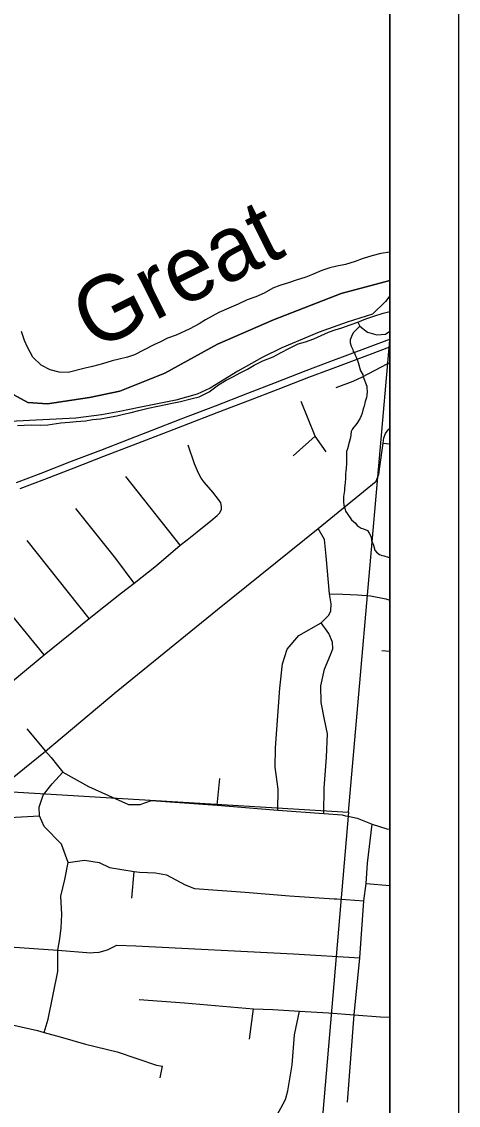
# Model space of a CAD drawing. Extents: x 0 to 34, y 0 to 22.
# Drawn here: x 8.362 to 9, y 18.183 to 19.765 of the extents above; entities that cross this region are included whole.
import ezdxf

# ---------------------------------------------------------------- set-up
doc = ezdxf.new("R2010")
doc.units = 0
for name, color, linetype in [('GM_X_City_Street', 7, 'Continuous'), ('GM_X_Corporation', 7, 'Continuous'), ('GM_X_County_Road', 7, 'Continuous'), ('GM_X_Major_River', 7, 'Continuous'), ('GM_X_Major_River_Text', 7, 'Continuous'), ('GM_X_Minor_River', 7, 'Continuous'), ('GM_X_State_Route', 7, 'Continuous'), ('SH_Data', 7, 'Continuous')]:
    doc.layers.add(name, color=color, linetype=linetype)

msp = doc.modelspace()

# ---------------------------------------------------------------- linework, layer by layer
at = {"layer": 'GM_X_City_Street'}
for p, q in [((8.7588, 19.1313), (8.7908, 19.1601)), ((8.5934, 19.0006), (8.5138, 19.101)), ((8.4606, 18.8937), (8.3698, 19.0073)), ((8.8883, 18.8469), (8.9, 18.8458)), ((8.6477, 18.6209), (8.6514, 18.6598)), ((8.2709, 18.5986), (8.3877, 18.6055)), ((8.5227, 18.4849), (8.5262, 18.5239)), ((8.8652, 18.5066), (8.9, 18.5036)), ((8.8223, 18.484), (8.8619, 18.481)), ((8.6947, 18.2791), (8.7005, 18.3236)), ((8.5642, 18.2229), (8.5677, 18.2397))]:
    msp.add_line(p, q, dxfattribs=at)
for points in [[(8.8215, 19.2312), (8.8463, 19.2404), (8.8597, 19.2465), (8.8958, 19.2654), (8.9, 19.2677)], [(8.8069, 19.137), (8.7908, 19.1601), (8.7701, 19.2104)], [(8.8899, 19.1495), (8.8911, 19.1574), (8.8937, 19.1638), (8.8974, 19.1693), (8.9, 19.1716)], [(8.654, 19.0528), (8.6539, 19.0573), (8.6527, 19.0623), (8.6494, 19.0676), (8.6412, 19.078), (8.6286, 19.0929), (8.6241, 19.0985), (8.62, 19.1059), (8.6145, 19.1193), (8.605, 19.1469)], [(8.88, 19.0943), (8.884, 19.1046), (8.8855, 19.1153), (8.8899, 19.1495)], [(7.9604, 18.3429), (8.0785, 18.443), (8.1263, 18.4819), (8.1779, 18.5241), (8.2709, 18.5986), (8.3967, 18.6996), (8.5001, 18.7867), (8.6479, 18.9068), (8.7952, 19.025), (8.88, 19.0943)], [(7.9831, 18.5148), (8.0096, 18.527), (8.0601, 18.5672), (8.1876, 18.6723), (8.1944, 18.6785), (8.2608, 18.7319), (8.3278, 18.7857), (8.3946, 18.8403), (8.4606, 18.8937), (8.4843, 18.9125), (8.5075, 18.931), (8.526, 18.9454), (8.5589, 18.9711), (8.5934, 19.0006), (8.6038, 19.0083), (8.6182, 19.0203), (8.6383, 19.0363), (8.6474, 19.0438), (8.6507, 19.0475), (8.654, 19.0528)], [(8.526, 18.9454), (8.4992, 18.9813), (8.4412, 19.0541)], [(8.7361, 18.6138), (8.7367, 18.6445), (8.7324, 18.6766), (8.7328, 18.7047), (8.739, 18.7917), (8.743, 18.8272), (8.7497, 18.8489), (8.7671, 18.8689), (8.7994, 18.8875), (8.8106, 18.8984), (8.8137, 18.9049), (8.8142, 18.9149), (8.8119, 18.9298), (8.8068, 18.9844), (8.8046, 19.0092), (8.7952, 19.025)], [(8.3946, 18.8403), (8.3276, 18.9225), (8.3187, 18.9352), (8.3103, 18.9485), (8.302, 18.9648)], [(8.8119, 18.9298), (8.8314, 18.9292), (8.8527, 18.928), (8.8717, 18.9267), (8.894, 18.9221), (8.9, 18.9205)], [(8.8032, 18.609), (8.8038, 18.6457), (8.8074, 18.691), (8.809, 18.7252), (8.8046, 18.7463), (8.7996, 18.771), (8.7991, 18.7952), (8.8046, 18.8194), (8.813, 18.8406), (8.8165, 18.8495), (8.8162, 18.8592), (8.8105, 18.8716), (8.7994, 18.8875)], [(8.3694, 18.7326), (8.3967, 18.6996), (8.4047, 18.6905), (8.4142, 18.6789), (8.4222, 18.669), (8.4597, 18.6483), (8.5177, 18.6218), (8.5349, 18.6218), (8.5514, 18.6279), (8.6477, 18.6209), (8.7361, 18.6138), (8.8032, 18.609), (8.8302, 18.6066), (8.8352, 18.6056)], [(8.3945, 18.2887), (8.4007, 18.3083), (8.4147, 18.3779), (8.4148, 18.4093), (8.4174, 18.4259), (8.4194, 18.442), (8.4204, 18.4614), (8.4189, 18.488), (8.4251, 18.5125), (8.4297, 18.537), (8.4198, 18.5639), (8.3945, 18.5897), (8.3877, 18.6055), (8.3874, 18.6178), (8.3932, 18.6358), (8.4063, 18.6523), (8.4222, 18.669)], [(8.8352, 18.6056), (8.8411, 18.6044), (8.8521, 18.6022), (8.874, 18.5933), (8.8953, 18.5863), (8.9, 18.5858)], [(8.8378, 18.1872), (8.8479, 18.3148), (8.8558, 18.3979), (8.8619, 18.481), (8.8652, 18.5066), (8.8673, 18.5364), (8.874, 18.5933)], [(8.4297, 18.537), (8.4534, 18.5408), (8.4749, 18.5373), (8.4903, 18.5299), (8.5262, 18.5239), (8.5338, 18.5229), (8.5574, 18.5219), (8.5737, 18.5194), (8.6009, 18.5044), (8.6143, 18.4993), (8.6886, 18.4938), (8.7532, 18.4886), (8.8183, 18.4843), (8.8223, 18.484)], [(8.0785, 18.443), (8.0916, 18.4385), (8.1341, 18.4343), (8.3091, 18.4164), (8.4148, 18.4093), (8.463, 18.4055), (8.467, 18.4057)], [(8.467, 18.4057), (8.4749, 18.4061), (8.4871, 18.4098), (8.5008, 18.4164), (8.5288, 18.4155), (8.7593, 18.4037), (8.8558, 18.3979)], [(7.5944, 18.3779), (7.6439, 18.3725), (7.6838, 18.3682), (7.7475, 18.3614), (7.8193, 18.3552), (7.8216, 18.355), (7.8546, 18.3522), (7.9604, 18.3429), (7.9962, 18.3397), (8.0146, 18.3381), (8.0724, 18.3329), (8.1174, 18.3288), (8.2145, 18.3208), (8.2997, 18.3107), (8.3851, 18.2916), (8.3945, 18.2887), (8.4179, 18.2828), (8.4549, 18.2717), (8.5013, 18.2607), (8.559, 18.2414), (8.5677, 18.2397)], [(8.5337, 18.3373), (8.5997, 18.3321), (8.7005, 18.3236), (8.7291, 18.3227), (8.7679, 18.32), (8.8104, 18.3175), (8.8479, 18.3148), (8.8862, 18.312), (8.9, 18.3112)], [(8.7799, 17.9607), (8.7514, 17.9623), (8.7401, 17.9675), (8.7297, 17.9787), (8.7228, 17.9955), (8.7215, 18.0263), (8.7285, 18.0726), (8.7308, 18.0957), (8.7272, 18.1228), (8.7259, 18.1403), (8.7331, 18.1653), (8.7406, 18.1786), (8.7472, 18.191), (8.751, 18.2035), (8.7572, 18.2416), (8.7607, 18.2853), (8.7679, 18.32)]]:
    msp.add_lwpolyline(points, dxfattribs=at)
at = {"layer": 'GM_X_Corporation'}
for points in [[(8.2412, 20.0451), (8.2346, 19.7113), (8.2293, 19.3521), (8.274, 19.3267), (8.2967, 19.3032), (8.3059, 19.2949), (8.3138, 19.2837), (8.3245, 19.2617), (8.3344, 19.2397), (8.3504, 19.2202), (8.3709, 19.2089), (8.3996, 19.2072), (8.461, 19.2162), (8.5053, 19.2254), (8.5711, 19.2518), (8.648, 19.2941), (8.73, 19.3298), (8.8288, 19.3684), (8.9, 19.3874), (8.9, 20.898)], [(8.9, 14.098), (8.9, 19.3874), (8.8288, 19.3684), (8.73, 19.3298), (8.648, 19.2941), (8.5711, 19.2518), (8.5053, 19.2254), (8.461, 19.2162), (8.3996, 19.2072), (8.3709, 19.2089), (8.3504, 19.2202), (8.3344, 19.2397), (8.3245, 19.2617), (8.3138, 19.2837), (8.3059, 19.2949), (8.2967, 19.3032), (8.274, 19.3267), (8.2293, 19.3521), (8.2346, 19.7113), (8.2412, 20.0451)], [(7.7682, 18.6757), (8.8396, 18.6106), (8.9, 19.3002), (8.9, 19.3647), (8.8935, 19.3564), (8.8746, 19.3383), (8.8373, 19.3265), (8.7964, 19.3118), (8.7418, 19.289), (8.7131, 19.2748), (8.6775, 19.2547), (8.6372, 19.2298), (8.6185, 19.2214), (8.5869, 19.2126), (8.5337, 19.2019), (8.5055, 19.1961), (8.4785, 19.1909), (8.4409, 19.186), (8.3446, 19.1811)], [(8.9, 14.098), (8.9, 19.185)], [(7.7459, 18.2415), (7.7682, 18.6757), (8.8396, 18.6106), (8.7511, 17.5795), (7.7161, 17.6636), (7.7361, 18.0529)]]:
    msp.add_lwpolyline(points, dxfattribs=at)
at = {"layer": 'GM_X_County_Road'}
msp.add_line((8.8899, 19.1495), (8.9, 19.1485), dxfattribs=at)
at = {"layer": 'GM_X_Major_River'}
for points in [[(8.9, 19.4286), (8.8869, 19.4265), (8.8736, 19.4233), (8.8594, 19.419), (8.8491, 19.4151)], [(8.9, 19.4286), (8.8869, 19.4265), (8.8736, 19.4233), (8.8594, 19.419), (8.8491, 19.4151)], [(8.8491, 19.4151), (8.835, 19.4108), (8.8224, 19.408), (8.8121, 19.4056), (8.8006, 19.402), (8.7868, 19.3962), (8.7769, 19.3922), (8.7631, 19.3876), (8.7532, 19.3844), (8.7391, 19.3801), (8.7291, 19.3761), (8.716, 19.3688), (8.7038, 19.3634), (8.6915, 19.3591), (8.6781, 19.3525), (8.6647, 19.3467), (8.6498, 19.3405), (8.6402, 19.335), (8.6306, 19.3299), (8.621, 19.324), (8.6075, 19.3167), (8.5876, 19.3073), (8.575, 19.303), (8.5646, 19.2979), (8.555, 19.2935), (8.5266, 19.2789), (8.5163, 19.2753), (8.5045, 19.2725), (8.4942, 19.2701), (8.4797, 19.2658), (8.4655, 19.2619), (8.4548, 19.2591), (8.4297, 19.2528), (8.4164, 19.2534), (8.4036, 19.2567), (8.3904, 19.2635), (8.3782, 19.2755), (8.3701, 19.2897), (8.3658, 19.2997), (8.3615, 19.313)], [(8.8491, 19.4151), (8.835, 19.4108), (8.8224, 19.408), (8.8121, 19.4056), (8.8006, 19.402), (8.7868, 19.3962), (8.7769, 19.3922), (8.7631, 19.3876), (8.7532, 19.3844), (8.7391, 19.3801), (8.7291, 19.3761), (8.716, 19.3688), (8.7038, 19.3634), (8.6915, 19.3591), (8.6781, 19.3525), (8.6647, 19.3467), (8.6498, 19.3405), (8.6402, 19.335), (8.6306, 19.3299), (8.621, 19.324), (8.6075, 19.3167), (8.5876, 19.3073), (8.575, 19.303), (8.5646, 19.2979), (8.555, 19.2935), (8.5266, 19.2789), (8.5163, 19.2753), (8.5045, 19.2725), (8.4942, 19.2701), (8.4797, 19.2658), (8.4655, 19.2619), (8.4548, 19.2591), (8.4297, 19.2528), (8.4164, 19.2534), (8.4036, 19.2567), (8.3904, 19.2635), (8.3782, 19.2755), (8.3701, 19.2897), (8.3658, 19.2997), (8.3615, 19.313)], [(8.3555, 19.1757), (8.3654, 19.1762), (8.3756, 19.1764), (8.3893, 19.1761), (8.3999, 19.1767), (8.4189, 19.1793), (8.4315, 19.1802), (8.4414, 19.1811), (8.4551, 19.1824), (8.4653, 19.1841), (8.4771, 19.1853), (8.487, 19.187), (8.5008, 19.1898), (8.5107, 19.1919), (8.5217, 19.1947), (8.5332, 19.1975), (8.5469, 19.201), (8.561, 19.2038), (8.5816, 19.2079), (8.5938, 19.2107), (8.6091, 19.2145), (8.6213, 19.2173), (8.6358, 19.2246), (8.6497, 19.235), (8.6609, 19.2416), (8.6713, 19.2471), (8.6812, 19.2526), (8.692, 19.258), (8.7016, 19.2635), (8.7142, 19.2697), (8.7292, 19.2759), (8.7403, 19.2817), (8.753, 19.2883), (8.766, 19.2949), (8.7767, 19.2977), (8.7886, 19.302), (8.7997, 19.3071), (8.81, 19.3118), (8.82, 19.3154), (8.8295, 19.3179), (8.8421, 19.3226), (8.8529, 19.3265), (8.8647, 19.3312), (8.8781, 19.3359), (8.8899, 19.3394), (8.9, 19.342)]]:
    msp.add_lwpolyline(points, dxfattribs=at)
at = {"layer": 'GM_X_Minor_River'}
for points in [[(8.8529, 19.3265), (8.8561, 19.3207), (8.867, 19.3118), (8.8809, 19.3081), (8.8935, 19.309), (8.9, 19.3131)], [(8.8561, 19.3207), (8.8463, 19.3107), (8.8439, 19.3054), (8.842, 19.3004), (8.842, 19.2963), (8.8435, 19.2913), (8.8457, 19.2864), (8.8461, 19.2837), (8.8483, 19.281), (8.8494, 19.278), (8.8505, 19.2753), (8.8524, 19.2704), (8.8535, 19.2677), (8.8572, 19.2555), (8.8602, 19.2502), (8.8609, 19.2468), (8.8661, 19.2331), (8.8665, 19.2297), (8.8668, 19.2255), (8.8664, 19.2194), (8.8656, 19.2164), (8.8637, 19.2107), (8.8625, 19.2035), (8.861, 19.1998), (8.8594, 19.1937), (8.8582, 19.1895), (8.8559, 19.1854), (8.854, 19.1824), (8.8525, 19.1797), (8.8502, 19.1767), (8.8468, 19.1726), (8.8448, 19.1696), (8.8433, 19.1669), (8.8425, 19.1578), (8.8409, 19.1525), (8.8378, 19.1412), (8.8367, 19.1374), (8.8366, 19.1207), (8.8361, 19.1127), (8.8357, 19.1093), (8.8353, 19.1044), (8.8353, 19.101), (8.8349, 19.0983), (8.8345, 19.0923), (8.834, 19.0885), (8.8336, 19.0839), (8.8336, 19.0805), (8.8324, 19.0718), (8.832, 19.0673), (8.832, 19.0639), (8.8327, 19.0593), (8.8334, 19.0566), (8.8353, 19.0505), (8.8375, 19.0471), (8.8439, 19.0376), (8.8499, 19.0326), (8.8521, 19.0295), (8.8578, 19.0257), (8.8612, 19.0245), (8.8672, 19.0222), (8.8698, 19.018), (8.8724, 19.0127), (8.8732, 19.0077), (8.8761, 19.0009), (8.878, 18.9933), (8.8802, 18.9906), (8.8847, 18.9871), (8.8874, 18.9863), (8.8912, 18.9852), (8.8976, 18.9832), (8.9, 18.9825)]]:
    msp.add_lwpolyline(points, dxfattribs=at)
at = {"layer": 'GM_X_State_Route'}
for points in [[(8.3542, 19.0921), (8.3904, 19.106), (8.4345, 19.1233), (8.4774, 19.1397), (8.5199, 19.1559), (8.5527, 19.1685), (8.5949, 19.1851), (8.6449, 19.2042), (8.6925, 19.2229), (8.7328, 19.2385), (8.7777, 19.2558), (8.8096, 19.2678), (8.8709, 19.2907), (8.9, 19.3015)], [(8.3596, 19.0833), (8.3956, 19.0972), (8.4386, 19.1139), (8.4819, 19.1305), (8.5254, 19.1472), (8.5568, 19.1594), (8.5975, 19.175), (8.6477, 19.1944), (8.6962, 19.2131), (8.7365, 19.2286), (8.7814, 19.246), (8.8133, 19.2579), (8.8718, 19.2799), (8.9, 19.2904)]]:
    msp.add_lwpolyline(points, dxfattribs=at)
at = {"layer": 'SH_Data'}
for p, q in [((9, 20.998), (9, 13.998)), ((8.9, 20.898), (8.9, 14.098))]:
    msp.add_line(p, q, dxfattribs=at)

# ---------------------------------------------------------------- texts
at = {"layer": 'GM_X_Major_River_Text'}
msp.add_text('Great', height=0.0947, rotation=26.554, dxfattribs=at).set_placement((8.4672, 19.2836))

doc.saveas('drawing.dxf')
